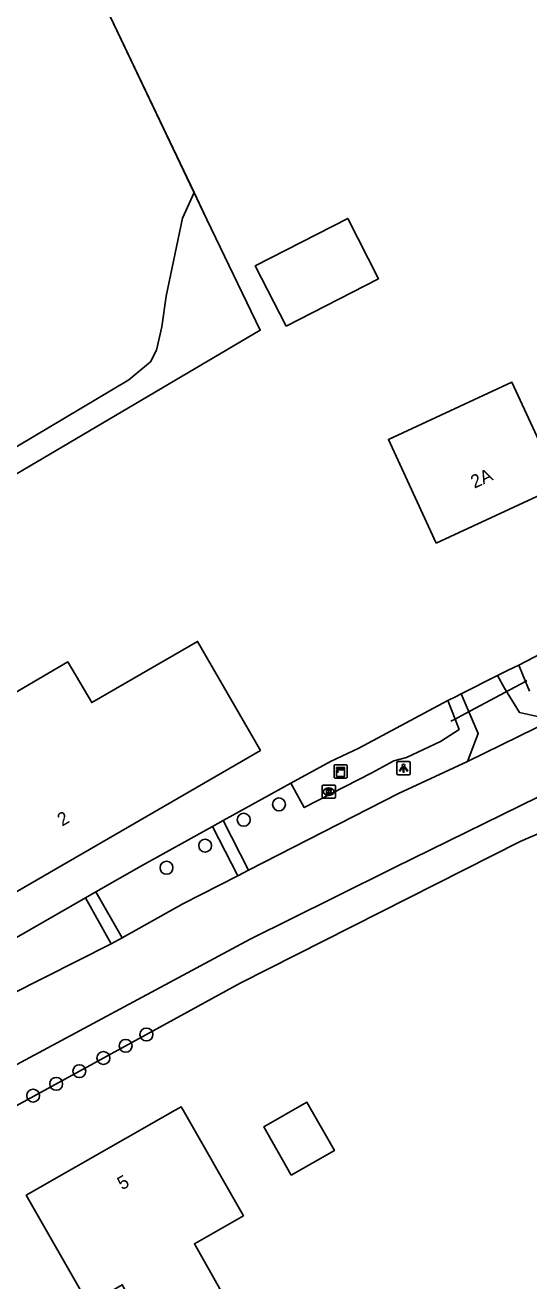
# Model space of a CAD drawing. Extents: x 164494 to 166241, y 382475 to 384494.
# Drawn here: x 165055.3 to 165093.4, y 382987.1 to 383082.1 of the extents above; entities that cross this region are included whole.
import ezdxf

# ---------------------------------------------------------------- set-up
doc = ezdxf.new("R2010")
doc.units = 0
for name, color, linetype in [('IMGEO_Boom', 7, 'Continuous'), ('IMGEO_Duiker', 7, 'Continuous'), ('IMGEO_Erf', 7, 'Continuous'), ('IMGEO_Grasland_agrarisch', 7, 'Continuous'), ('IMGEO_Grasland_overig', 7, 'Continuous'), ('IMGEO_Groenvoorziening', 7, 'Continuous'), ('IMGEO_Hek', 7, 'Continuous'), ('IMGEO_Kast', 7, 'Continuous'), ('IMGEO_Lichtpunt', 7, 'Continuous'), ('IMGEO_Pand', 7, 'Continuous'), ('IMGEO_Pand_nummerreeks', 7, 'Continuous'), ('IMGEO_Rijbaan_lokaal_gesloten', 7, 'Continuous'), ('IMGEO_Rijbaan_lokaal_open', 7, 'Continuous'), ('IMGEO_Rioolput', 7, 'Continuous'), ('IMGEO_Voetpad_halfverhard', 7, 'Continuous')]:
    doc.layers.add(name, color=color, linetype=linetype)

msp = doc.modelspace()

# ---------------------------------------------------------------- linework, layer by layer
at = {"layer": 'IMGEO_Boom'}
for centre in [(165074.517, 383023.125), (165071.85, 383021.959), (165068.928, 383020.005), (165066.006, 383018.33), (165064.486, 383005.721), (165062.917, 383004.863), (165061.232, 383003.941), (165059.408, 383002.943), (165057.657, 383001.986), (165055.911, 383001.095)]:
    msp.add_circle(centre, 0.489, dxfattribs=at)
at = {"layer": 'IMGEO_Duiker'}
msp.add_lwpolyline([(165093.282, 383032.484), (165093.164, 383032.421), (165092.411, 383032.019), (165088.575, 383029.973), (165087.842, 383029.582), (165087.517, 383029.409)], dxfattribs=at)
at = {"layer": 'IMGEO_Erf'}
msp.add_lwpolyline([(165092.654, 383033.657), (165109.176, 383042.267), (165126.099, 383051.085), (165129.346, 383052.646), (165106.891, 383080.948), (165095.917, 383095.847), (165095.148, 383097.711), (165091.308, 383102.836)], dxfattribs=at)
at = {"layer": 'IMGEO_Grasland_agrarisch'}
msp.add_lwpolyline([(165068.089, 383069.395), (165060.973, 383084.346), (165091.308, 383102.836)], dxfattribs=at)
at = {"layer": 'IMGEO_Grasland_overig'}
for points in [[(165036.078, 383000.775), (165034.033, 383004.728), (165028.522, 383018.014), (165027.072, 383024.353), (165026.884, 383026.266), (165027.547, 383029.137), (165028.147, 383031.534), (165029.157, 383034.09), (165030.862, 383035.794), (165036.922, 383039.619), (165063.156, 383055.236), (165064.802, 383056.611), (165065.252, 383057.472), (165065.659, 383059.237), (165065.971, 383061.567), (165067.204, 383067.462), (165068.089, 383069.395)], [(165068.089, 383069.395), (165069.056, 383067.363), (165073.095, 383058.987), (165036.723, 383037.565), (165031.74, 383031.555), (165029.711, 383023.792), (165032.253, 383014.941)]]:
    msp.add_lwpolyline(points, dxfattribs=at)
at = {"layer": 'IMGEO_Groenvoorziening'}
for points in [[(165091.062, 383032.863), (165091.867, 383033.265), (165092.654, 383033.657)], [(165092.654, 383033.657), (165093.164, 383032.421), (165093.464, 383031.692)], [(165087.302, 383030.987), (165087.92, 383031.295), (165088.293, 383031.481)], [(165075.419, 383024.723), (165078.42, 383026.378), (165080.567, 383027.366), (165086.908, 383030.775), (165087.302, 383030.987)], [(165087.302, 383030.987), (165087.842, 383029.582), (165088.149, 383028.783), (165086.745, 383027.872), (165084.158, 383026.667), (165083.217, 383026.412), (165081.553, 383025.502), (165076.433, 383022.884), (165075.419, 383024.723)], [(165070.298, 383021.899), (165075.419, 383024.723)], [(165097.081, 383022.184), (165092.763, 383020.321), (165071.589, 383009.606), (165052.261, 382999.034)], [(165060.66, 383016.51), (165064.101, 383018.481), (165069.494, 383021.455)], [(165047.036, 383008.706), (165059.881, 383016.064)]]:
    msp.add_lwpolyline(points, dxfattribs=at)
at = {"layer": 'IMGEO_Hek'}
for points in [[(165069.056, 383067.363), (165060.973, 383084.346)], [(165071.589, 383009.606), (165092.763, 383020.321)]]:
    msp.add_lwpolyline(points, dxfattribs=at)
at = {"layer": 'IMGEO_Kast'}
for p, q in [((165078.681, 383025.188), (165078.681, 383026.029)), ((165078.681, 383026.029), (165078.681, 383025.188)), ((165078.756, 383026.113), (165079.597, 383026.113)), ((165079.597, 383026.113), (165078.756, 383026.113)), ((165079.681, 383026.038), (165079.681, 383025.197)), ((165079.681, 383025.197), (165079.681, 383026.038)), ((165079.606, 383025.113), (165078.765, 383025.113)), ((165078.765, 383025.113), (165079.606, 383025.113))]:
    msp.add_line(p, q, dxfattribs=at)
for points in [[(165078.876, 383025.903), (165079.476, 383025.903), (165079.476, 383025.818), (165078.876, 383025.818), (165078.876, 383025.903)], [(165078.876, 383025.728), (165079.476, 383025.728), (165079.476, 383025.239), (165078.876, 383025.239), (165078.876, 383025.728)]]:
    msp.add_lwpolyline(points, dxfattribs=at)
msp.add_circle((165078.96, 383025.577), 0.0377, dxfattribs=at)
for centre, start, end in [((165078.759, 383026.035), 92.4484, 184.28452), ((165078.759, 383026.035), 92.4484, 184.28452), ((165079.603, 383026.035), 2.4484, 94.28452), ((165079.603, 383026.035), 2.4484, 94.28452), ((165078.759, 383025.191), 182.4484, 274.28452), ((165078.759, 383025.191), 182.4484, 274.28452), ((165079.603, 383025.191), 272.4484, 4.28452), ((165079.603, 383025.191), 272.4484, 4.28452)]:
    msp.add_arc(centre, 0.0779, start, end, dxfattribs=at)
at = {"layer": 'IMGEO_Lichtpunt'}
for p, q in [((165084.346, 383026.361), (165083.538, 383026.361)), ((165084.346, 383026.361), (165083.538, 383026.361)), ((165083.444, 383026.266), (165083.444, 383025.459)), ((165083.444, 383026.266), (165083.444, 383025.459)), ((165083.538, 383025.365), (165084.346, 383025.365)), ((165083.538, 383025.365), (165084.346, 383025.365)), ((165084.44, 383025.459), (165084.44, 383026.266)), ((165084.44, 383025.459), (165084.44, 383026.266))]:
    msp.add_line(p, q, dxfattribs=at)
for points in [[(165083.818, 383025.93), (165083.857, 383025.902), (165083.669, 383025.64), (165083.631, 383025.667), (165083.818, 383025.93)], [(165083.92, 383025.882), (165083.967, 383025.882), (165083.967, 383025.56), (165083.92, 383025.56), (165083.92, 383025.882)], [(165084.03, 383025.902), (165084.068, 383025.929), (165084.255, 383025.667), (165084.216, 383025.639), (165084.03, 383025.902)]]:
    msp.add_lwpolyline(points, dxfattribs=at)
msp.add_circle((165083.943, 383026.064), 0.0994, dxfattribs=at)
for centre, start, end in [((165083.538, 383026.266), 90, 180), ((165083.538, 383026.266), 90, 180), ((165084.346, 383026.266), 0, 90), ((165084.346, 383026.266), 0, 90), ((165083.538, 383025.459), 180, 270), ((165083.538, 383025.459), 180, 270), ((165084.346, 383025.459), 270, 0), ((165084.346, 383025.459), 270, 360)]:
    msp.add_arc(centre, 0.0946, start, end, dxfattribs=at)
at = {"layer": 'IMGEO_Pand'}
for points in [[(165075.058, 383059.299), (165072.724, 383063.863), (165079.723, 383067.443), (165082.057, 383062.879), (165075.058, 383059.299)], [(165086.419, 383042.886), (165082.794, 383050.728), (165092.141, 383055.049), (165095.767, 383047.208), (165086.419, 383042.886)], [(165073.128, 383027.21), (165046.076, 383011.575), (165041.243, 383019.806), (165048.824, 383024.256), (165054.61, 383027.653), (165052.965, 383030.653), (165058.527, 383033.919), (165060.345, 383030.823), (165068.361, 383035.457), (165073.128, 383027.21)], [(165067.253, 383000), (165067.108, 383000.254), (165066.663, 383000), (165055.39, 382993.559), (165060.095, 382985.325), (165062.655, 382986.784), (165064.694, 382983.206), (165070.149, 382986.314), (165068.111, 382989.892), (165071.821, 382992.006), (165067.253, 383000)], [(165075.449, 382995.069), (165078.714, 382996.935), (165076.626, 383000.591), (165073.363, 382998.726), (165075.449, 382995.069)]]:
    msp.add_lwpolyline(points, dxfattribs=at)
at = {"layer": 'IMGEO_Rijbaan_lokaal_gesloten'}
for points in [[(165088.775, 383026.373), (165095.219, 383029.526)], [(165072.217, 383018.147), (165083.565, 383023.951), (165088.775, 383026.373)], [(165050.894, 383001.427), (165072.324, 383012.931), (165078.697, 383016.073), (165083.246, 383018.36), (165095.49, 383024.344)], [(165071.399, 383017.729), (165072.217, 383018.147)], [(165062.647, 383013.041), (165067.244, 383015.604), (165071.399, 383017.729)], [(165061.822, 383012.581), (165062.647, 383013.041)], [(165048.666, 383005.698), (165048.937, 383005.869), (165054.231, 383008.739), (165061.822, 383012.581)]]:
    msp.add_lwpolyline(points, dxfattribs=at)
at = {"layer": 'IMGEO_Rijbaan_lokaal_open'}
for points in [[(165091.062, 383032.863), (165088.293, 383031.481)], [(165095.219, 383029.526), (165092.716, 383030.076), (165091.582, 383031.909), (165091.062, 383032.863)], [(165088.293, 383031.481), (165089.6, 383028.476), (165088.775, 383026.373)]]:
    msp.add_lwpolyline(points, dxfattribs=at)
at = {"layer": 'IMGEO_Rioolput'}
for p, q in [((165077.78, 383023.66), (165077.78, 383024.512)), ((165077.855, 383024.586), (165078.707, 383024.586)), ((165078.781, 383024.512), (165078.781, 383023.66)), ((165078.707, 383023.586), (165077.855, 383023.586)), ((165078.291, 383023.806), (165078.266, 383023.806)), ((165078.268, 383024.366), (165078.293, 383024.366))]:
    msp.add_line(p, q, dxfattribs=at)
for points in [[(165077.78, 383023.66), (165077.78, 383024.512)], [(165077.855, 383024.586), (165078.707, 383024.586)], [(165078.781, 383024.512), (165078.781, 383023.66)], [(165078.707, 383023.586), (165077.855, 383023.586)], [(165078.369, 383024.284), (165078.117, 383024.286), (165078.117, 383023.886)], [(165078.117, 383023.886), (165078.241, 383023.886), (165078.241, 383024.048), (165078.252, 383024.048)], [(165078.295, 383024.205), (165078.241, 383024.205), (165078.241, 383024.124)], [(165078.241, 383024.124), (165078.293, 383024.124)], [(165078.299, 383024.019), (165078.37, 383023.886), (165078.51, 383023.886), (165078.445, 383024.012)]]:
    msp.add_lwpolyline(points, dxfattribs=at)
for centre, radius, start, end in [((165077.857, 383024.51), 0.0765, 91.55205, 178.44795), ((165077.857, 383024.51), 0.0765, 91.55205, 178.44795), ((165078.705, 383024.51), 0.0765, 1.55205, 88.44795), ((165078.705, 383024.51), 0.0765, 1.55205, 88.44795), ((165077.857, 383023.662), 0.0765, 181.55205, 268.44795), ((165077.857, 383023.662), 0.0765, 181.55205, 268.44795), ((165078.251, 383023.995), 0.0533, 26.02933, 88.69889), ((165078.277, 383024.313), 0.19, 274.7715, 282.96867), ((165078.301, 383024.109), 0.0964, 77.00612, 93.18647), ((165078.315, 383024.166), 0.0378, 276.66336, 79.67722), ((165078.368, 383024.174), 0.109, 350.36119, 89.41601), ((165078.366, 383024.174), 0.112, 277.58423, 350.98172), ((165078.35, 383023.959), 0.108, 29.51342, 73.79051), ((165078.705, 383023.662), 0.0765, 271.55205, 358.44795), ((165078.705, 383023.662), 0.0765, 271.55205, 358.44795)]:
    msp.add_arc(centre, radius, start, end, dxfattribs=at)
for centre, major_axis, ratio, start_param, end_param in [((165078.267, 383024.086), (-0.387, 0.002), 0.722429, 4.712389, 7.853982), ((165078.292, 383024.086), (-0.39, 0.002), 0.717154, 1.570796, 4.712389)]:
    msp.add_ellipse(centre, major_axis=major_axis, ratio=ratio, start_param=start_param, end_param=end_param, dxfattribs=at)
at = {"layer": 'IMGEO_Voetpad_halfverhard'}
for points in [[(165069.494, 383021.455), (165070.298, 383021.899)], [(165070.298, 383021.899), (165072.217, 383018.147)], [(165071.399, 383017.729), (165069.494, 383021.455)], [(165059.881, 383016.064), (165060.66, 383016.51)], [(165061.822, 383012.581), (165059.881, 383016.064)], [(165060.66, 383016.51), (165062.647, 383013.041)]]:
    msp.add_lwpolyline(points, dxfattribs=at)

# ---------------------------------------------------------------- texts
at = {"layer": 'IMGEO_Pand_nummerreeks'}
for s, rotation, p in [('2A', 24.81322, (165089.305, 383046.997)), ('2', 30.02624, (165058.102, 383021.436)), ('5', 29.74224, (165062.638, 382993.922))]:
    msp.add_text(s, height=1, rotation=rotation, dxfattribs=at).set_placement(p)

doc.saveas('drawing.dxf')
